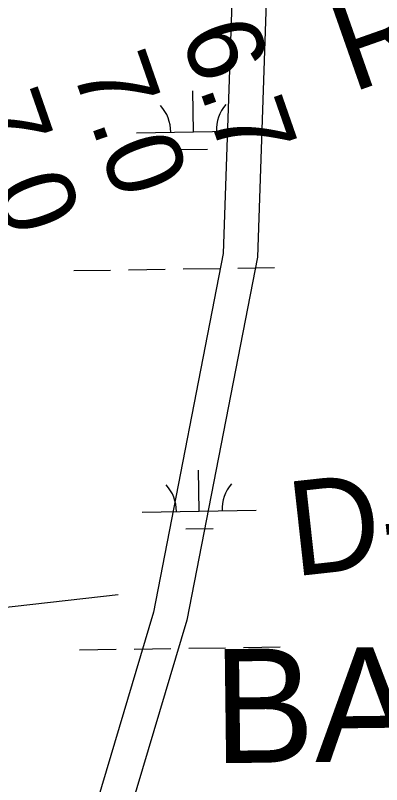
# Model space of a CAD drawing. Extents: x 3807117 to 3845308, y 337856 to 363736.
# Drawn here: x 3834041 to 3834362, y 346961 to 347636 of the extents above; entities that cross this region are included whole.
import ezdxf

# ---------------------------------------------------------------- set-up
doc = ezdxf.new("R2010")
doc.units = 0
for name, color, linetype in [('V-CHAN-NAID', 7, 'Continuous'), ('V-RIVR-RANG', 7, 'Continuous'), ('V-RIVR-RANG-IDEN', 7, 'Continuous'), ('V-ROAD-CNTR', 7, 'Continuous'), ('V-WETL-SWMP', 7, 'Continuous')]:
    doc.layers.add(name, color=color, linetype=linetype)

msp = doc.modelspace()

# ---------------------------------------------------------------- linework, layer by layer
at = {"layer": 'V-RIVR-RANG'}
msp.add_line((3834131.06, 347127.63), (3833137.37, 347015.54), dxfattribs=at)
at = {"layer": 'V-ROAD-CNTR'}
for points in [[(3831835.02, 350986.74), (3832411.15, 350479.09), (3832910.37, 350016.21), (3833595.35, 349381.1), (3833766.7, 349184.41), (3834132.75, 348363.19), (3834265.97, 347794.44), (3834253.27, 347423.69), (3834191.22, 347105.36), (3834089.54, 346764.36), (3834056.41, 346524.51), (3834053.82, 346408.88), (3834082.16, 346293.68), (3834179.52, 346287.04), (3834268.87, 346281.79), (3834321.19, 346229.47), (3834326.51, 346154.93)], [(3831816.69, 350962.91), (3832391.03, 350456.83), (3832889.97, 349994.21), (3833573.79, 349360.19), (3833741.13, 349168.1), (3834104.19, 348353.58), (3834235.85, 347791.48), (3834223.37, 347427.09), (3834162.06, 347112.54), (3834060.13, 346770.73), (3834026.46, 346526.91), (3834023.74, 346405.58), (3834058.26, 346265.24), (3834177.62, 346257.1), (3834255.72, 346252.51), (3834292.06, 346216.17), (3834296.59, 346152.79)]]:
    msp.add_lwpolyline(points, dxfattribs=at)
at = {"layer": 'V-WETL-SWMP'}
for p, q in [((3834197.27, 347533.65), (3834196.73, 347569.65)), ((3834147.27, 347532.9), (3834247.26, 347534.4)), ((3834185.5, 347518.04), (3834209.5, 347518.4)), ((3834236.22, 347414.15), (3834268.21, 347414.63)), ((3834092.23, 347411.99), (3834124.23, 347412.47)), ((3834140.23, 347412.71), (3834172.22, 347413.19)), ((3834188.22, 347413.43), (3834220.22, 347413.91)), ((3834202.25, 347201.01), (3834201.71, 347237.01)), ((3834152.25, 347200.26), (3834252.24, 347201.76)), ((3834190.48, 347185.4), (3834214.48, 347185.76)), ((3834097.22, 347079.36), (3834129.21, 347079.84)), ((3834145.21, 347080.07), (3834177.21, 347080.55)), ((3834193.21, 347080.79), (3834225.2, 347081.27)), ((3834241.2, 347081.51), (3834273.2, 347081.99))]:
    msp.add_line(p, q, dxfattribs=at)
for centre, start, end in [((3834142.02, 347533.3), 0.08653, 41.63019), ((3834252.5, 347534.95), 140.08653, 181.63019), ((3834147.01, 347200.66), 0.08653, 41.63019), ((3834257.48, 347202.32), 140.08653, 181.63019)]:
    msp.add_arc(centre, 35.25, start, end, dxfattribs=at)

# ---------------------------------------------------------------- texts
at = {"layer": 'V-CHAN-NAID'}
msp.add_text('BAYOU LAMOQUE', height=100, rotation=0.71171, dxfattribs=at).set_placement((3834214.89, 346979.88))
at = {"layer": 'V-RIVR-RANG'}
for s, p in [('6.7', (3834185.3, 347619.4)), ('7.0', (3834090.01, 347588.96)), ('7.0', (3833995.67, 347555.79))]:
    msp.add_text(s, height=67, rotation=289.23833, dxfattribs=at).set_placement(p)
at = {"layer": 'V-RIVR-RANG-IDEN'}
for s, rotation, p in [('R-33.2', 19.37717, (3834335.9, 347567.73)), ('D-020', 6.29433, (3834285.37, 347143.68))]:
    msp.add_text(s, height=83, rotation=rotation, dxfattribs=at).set_placement(p)

doc.saveas('drawing.dxf')
